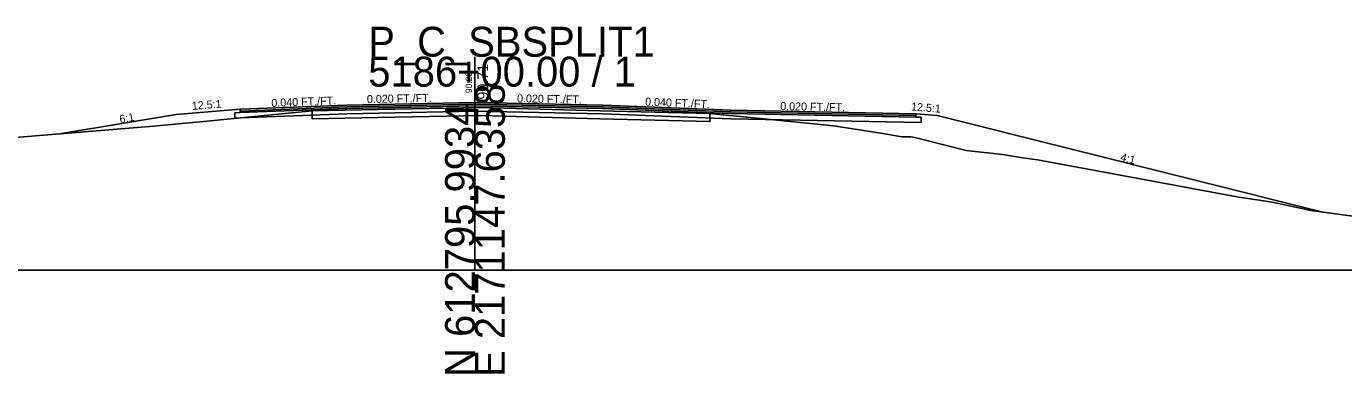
# Model space of a CAD drawing. Extents: x -26 to 1303, y -3010 to 12023.
# Drawn here: x 107.9 to 231.4, y 7490.3 to 7522.8 of the extents above; entities that cross this region are included whole.
import ezdxf

# ---------------------------------------------------------------- set-up
doc = ezdxf.new("R2010")
doc.units = 0
for name, color, linetype in [('RD_GPK_XS_Cell', 7, 'Continuous'), ('RD_XS_Base', 7, 'Continuous'), ('RD_XS_ExGround', 7, 'Continuous'), ('RD_XS_ExPaveRet', 7, 'Continuous'), ('RD_XS_Greenside', 7, 'Continuous'), ('RD_XS_Pave', 7, 'Continuous'), ('RD_XS_PaveOvlay_CP', 7, 'Continuous'), ('RD_XS_TieSlope', 7, 'Continuous'), ('RD_XS_TX_Elev_EX', 7, 'Continuous'), ('RD_XS_TX_Elev_PR', 7, 'Continuous'), ('RD_XS_TX_ShdSlope', 7, 'Continuous'), ('RD_XS_TX_Slope', 7, 'Continuous')]:
    doc.layers.add(name, color=color, linetype=linetype)

msp = doc.modelspace()

# ---------------------------------------------------------------- linework, layer by layer
at = {"layer": 'RD_GPK_XS_Cell'}
for p, q in [((150, 7500), (150, 7520)), ((0, 7500), (150, 7500)), ((150, 7500), (300, 7500))]:
    msp.add_line(p, q, dxfattribs=at)
at = {"layer": 'RD_XS_Base'}
for p, q in [((138, 7515.16), (128, 7514.76)), ((136, 7515.08), (136, 7515.08)), ((150, 7515.4), (138, 7515.16)), ((150, 7514.9), (150, 7515.55)), ((150, 7515.55), (150, 7515.55)), ((150, 7515.55), (150, 7515.55)), ((150, 7515.55), (150, 7515.4)), ((150, 7515.4), (150, 7515.4)), ((150, 7515.4), (162, 7515.16)), ((150, 7515.4), (150, 7515.4)), ((150, 7514.9), (150, 7515.4)), ((150, 7515.4), (150, 7515.4)), ((150, 7515.4), (150, 7515.4)), ((162, 7515.16), (162, 7515.16)), ((162, 7515.16), (174, 7514.68)), ((128, 7514.76), (127.5, 7514.74)), ((127.5, 7514.74), (127.5, 7514.74)), ((127.5, 7514.74), (127.5, 7514.24)), ((127.5, 7514.24), (128, 7514.26)), ((128, 7514.76), (128, 7514.76)), ((128, 7514.26), (138, 7514.66)), ((128, 7514.26), (128, 7514.26)), ((136, 7514.58), (136, 7514.58)), ((138, 7514.66), (150, 7514.9)), ((162, 7514.66), (150, 7514.9)), ((150, 7514.9), (150, 7514.9)), ((150, 7514.9), (150, 7514.9)), ((174, 7514.18), (162, 7514.66)), ((162, 7514.66), (162, 7514.66)), ((174, 7514.68), (174, 7514.68)), ((174, 7514.68), (191.32, 7514.33)), ((191.82, 7513.82), (174, 7514.18)), ((174, 7514.18), (174, 7514.18)), ((191.32, 7514.33), (191.32, 7514.33)), ((191.32, 7514.33), (191.82, 7514.32)), ((191.82, 7514.32), (191.82, 7514.32)), ((191.82, 7514.32), (191.82, 7513.82))]:
    msp.add_line(p, q, dxfattribs=at)
at = {"layer": 'RD_XS_ExGround'}
msp.add_lwpolyline([(104.96, 7512.27), (111.88, 7512.85), (119.87, 7513.5), (124.54, 7513.93), (134.75, 7514.92), (140.92, 7515.05), (150.52, 7515.24), (161.72, 7514.93), (172.03, 7514.67), (182.38, 7513.65), (183.82, 7513.5), (188.41, 7512.77), (190.02, 7512.48), (190.86, 7512.49), (191.08, 7512.45), (191.85, 7512.28), (196.06, 7511.22), (199.44, 7510.85), (201.34, 7510.52), (202.72, 7510.35), (210.67, 7508.86), (214.55, 7508.15), (221.61, 7506.83), (223.93, 7506.5), (224.87, 7506.35), (228.36, 7505.6), (234.39, 7504.79)], dxfattribs=at)
at = {"layer": 'RD_XS_ExPaveRet'}
for points in [[(161.72, 7514.93), (150.52, 7515.24), (150.52, 7515.24), (150.52, 7515.24), (140.92, 7515.05), (140.92, 7515.05), (134.75, 7514.92), (134.75, 7514.17), (134.75, 7514.17), (140.92, 7514.3), (140.92, 7514.3), (150.52, 7514.49), (150.52, 7514.49), (150.52, 7514.49), (161.72, 7514.18), (161.72, 7514.18), (172.03, 7513.92), (172.03, 7514.67), (172.03, 7514.67), (161.72, 7514.93), (161.72, 7514.93)], [(161.72, 7514.93), (150.52, 7515.24), (140.92, 7515.05), (134.75, 7514.92), (134.75, 7514.17), (140.92, 7514.3), (150.52, 7514.49), (161.72, 7514.18), (172.03, 7513.92), (172.03, 7514.67), (161.72, 7514.93)]]:
    msp.add_lwpolyline(points, dxfattribs=at)
at = {"layer": 'RD_XS_Greenside'}
for p, q in [((122, 7514.59), (111.23, 7512.8)), ((193.32, 7514.49), (229.48, 7505.45))]:
    msp.add_line(p, q, dxfattribs=at)
at = {"layer": 'RD_XS_Pave'}
for p, q in [((138, 7515.47), (128, 7515.07)), ((138, 7515.31), (128, 7514.91)), ((128, 7514.91), (138, 7515.31)), ((128, 7514.76), (138, 7515.16)), ((128, 7515.07), (128, 7515.07)), ((128, 7515.07), (128, 7514.91)), ((136, 7515.39), (136, 7515.39)), ((136, 7515.23), (136, 7515.23)), ((136, 7515.23), (136, 7515.23)), ((136, 7515.08), (136, 7515.08)), ((150, 7515.71), (138, 7515.47)), ((150, 7515.55), (138, 7515.31)), ((138, 7515.31), (150, 7515.55)), ((138, 7515.16), (150, 7515.4)), ((162, 7515.47), (150, 7515.71)), ((150, 7515.71), (150, 7515.71)), ((150, 7515.71), (150, 7515.71)), ((150, 7515.4), (150, 7515.55)), ((150, 7515.55), (150, 7515.55)), ((150, 7515.55), (150, 7515.55)), ((150, 7515.55), (150, 7515.55)), ((150, 7515.55), (150, 7515.55)), ((150, 7515.55), (162, 7515.31)), ((162, 7515.31), (150, 7515.55)), ((150, 7515.55), (150, 7515.55)), ((150, 7515.55), (150, 7515.55)), ((150, 7515.55), (150, 7515.55)), ((150, 7515.55), (150, 7515.4)), ((150, 7515.4), (150, 7515.4)), ((150, 7515.4), (150, 7515.4)), ((150, 7515.4), (150, 7515.4)), ((150, 7515.4), (162, 7515.16)), ((174, 7514.99), (162, 7515.47)), ((162, 7515.47), (162, 7515.47)), ((162, 7515.31), (162, 7515.31)), ((162, 7515.31), (174, 7514.83)), ((174, 7514.83), (162, 7515.31)), ((162, 7515.31), (162, 7515.31)), ((162, 7515.16), (162, 7515.16)), ((162, 7515.16), (174, 7514.68)), ((128, 7514.91), (128, 7514.91)), ((128, 7514.91), (128, 7514.76)), ((191.32, 7514.65), (174, 7514.99)), ((174, 7514.99), (174, 7514.99)), ((174, 7514.83), (174, 7514.83)), ((174, 7514.83), (191.32, 7514.49)), ((191.32, 7514.49), (174, 7514.83)), ((174, 7514.83), (174, 7514.83)), ((174, 7514.68), (191.32, 7514.33)), ((174, 7514.68), (174, 7514.68)), ((191.32, 7514.49), (191.32, 7514.65)), ((191.32, 7514.65), (191.32, 7514.65)), ((191.32, 7514.33), (191.32, 7514.49)), ((191.32, 7514.49), (191.32, 7514.49))]:
    msp.add_line(p, q, dxfattribs=at)
at = {"layer": 'RD_XS_PaveOvlay_CP'}
for p, q in [((138, 7515.47), (128, 7515.07)), ((136, 7515.39), (136, 7515.39)), ((150, 7515.71), (138, 7515.47)), ((162, 7515.47), (150, 7515.71)), ((150, 7515.71), (150, 7515.71)), ((150, 7515.71), (150, 7515.71)), ((174, 7514.99), (162, 7515.47)), ((162, 7515.47), (162, 7515.47)), ((191.32, 7514.65), (174, 7514.99)), ((174, 7514.99), (174, 7514.99))]:
    msp.add_line(p, q, dxfattribs=at)
at = {"layer": 'RD_XS_TieSlope'}
for p, q in [((128, 7515.07), (122, 7514.59)), ((191.32, 7514.65), (193.32, 7514.49))]:
    msp.add_line(p, q, dxfattribs=at)

# ---------------------------------------------------------------- texts
at = {"layer": 'RD_GPK_XS_Cell'}
for s, p in [('P_C_SBSPLIT1', (140, 7520)), ('5186+00.00 / 1', (140, 7517.2))]:
    msp.add_text(s, height=2.8, dxfattribs=at).set_placement(p)
for s, p in [('E 2171147.6358', (152.8, 7490)), ('N 612795.9934', (150, 7490))]:
    msp.add_text(s, height=2.8, rotation=90, dxfattribs=at).set_placement(p)
at = {"layer": 'RD_XS_TX_Elev_EX'}
msp.add_text('90.23', height=0.6, rotation=90, dxfattribs=at).set_placement((149.72, 7516.58))
at = {"layer": 'RD_XS_TX_Elev_PR'}
msp.add_text('90.71', height=1, rotation=90, dxfattribs=at).set_placement((151.23, 7515.98))
at = {"layer": 'RD_XS_TX_ShdSlope'}
for rotation, p in [(4.5739, (123.49, 7515.01)), (355.4261, (190.86, 7514.97))]:
    msp.add_text('12.5:1', height=0.75, rotation=rotation, dxfattribs=at).set_placement(p)
at = {"layer": 'RD_XS_TX_Slope'}
for s, rotation, p in [('0.040 FT./FT.', 2.2906, (130.93, 7515.29)), ('0.020 FT./FT.', 1.1458, (139.88, 7515.65)), ('0.020 FT./FT.', 358.8542, (153.94, 7515.73)), ('0.040 FT./FT.', 357.7094, (165.94, 7515.42)), ('0.020 FT./FT.', 358.8542, (178.61, 7515)), ('6:1', 9.4623, (116.74, 7513.77)), ('4:1', 345.9638, (210.45, 7510.26))]:
    msp.add_text(s, height=0.75, rotation=rotation, dxfattribs=at).set_placement(p)

doc.saveas('drawing.dxf')
